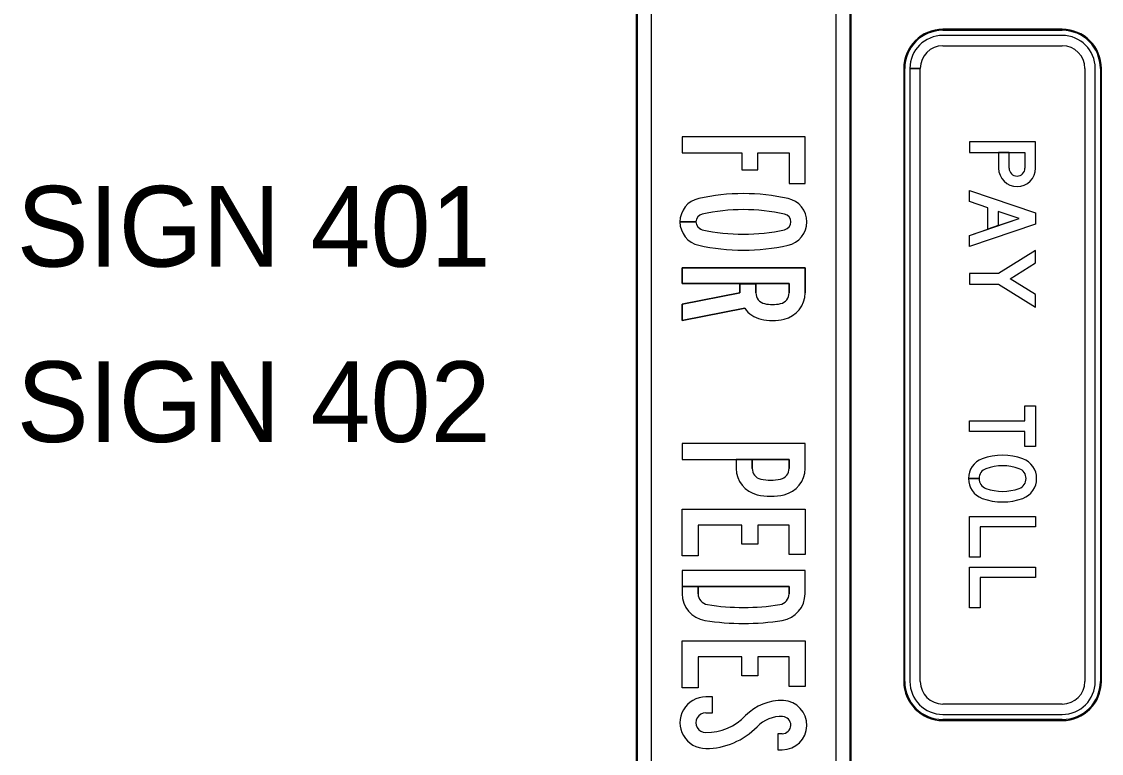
# Model space of a CAD drawing. Extents: x 524708 to 525491, y 1531861 to 1532506.
# Drawn here: x 525015.42 to 525062.25, y 1532201.55 to 1532233.31 of the extents above; entities that cross this region are included whole.
import ezdxf

# ---------------------------------------------------------------- set-up
doc = ezdxf.new("R2010")
doc.units = 0
for name, color, linetype in [('GSBWFill', 7, 'Continuous'), ('GSColorFill', 7, 'Continuous'), ('GSOutline', 7, 'Continuous'), ('TextLabel', 7, 'Continuous')]:
    doc.layers.add(name, color=color, linetype=linetype)

msp = doc.modelspace()

# ---------------------------------------------------------------- linework, layer by layer
at = {"layer": 'GSBWFill'}
for p, q in [((525058.932, 1532227.631), (525058.932, 1532226.945)), ((525044.663, 1532224.613), (525043.97, 1532224.613)), ((525043.97, 1532224.612), (525044.663, 1532224.612)), ((525046.57, 1532221.533), (525046.57, 1532221.932)), ((525046.41, 1532214.306), (525046.41, 1532213.916)), ((525056.939, 1532213.474), (525056.482, 1532213.474)), ((525056.482, 1532213.473), (525056.939, 1532213.473))]:
    msp.add_line(p, q, dxfattribs=at)
for points in [[(525044.063, 1532227.613), (525046.65, 1532227.613), (525046.65, 1532226.866), (525047.343, 1532226.866), (525047.343, 1532227.613), (525048.703, 1532227.613), (525048.703, 1532226.279), (525049.397, 1532226.279), (525049.397, 1532228.306), (525044.063, 1532228.306)], [(525056.532, 1532225.974), (525059.389, 1532225.002), (525059.389, 1532224.516), (525056.532, 1532223.545), (525056.532, 1532224.028), (525058.683, 1532224.759), (525057.774, 1532225.068), (525057.774, 1532224.45), (525057.317, 1532224.295), (525057.317, 1532225.224), (525056.532, 1532225.491)], [(525056.532, 1532222.374), (525056.532, 1532221.916), (525057.789, 1532221.916), (525059.389, 1532220.916), (525059.389, 1532221.455), (525058.286, 1532222.145), (525059.389, 1532222.834), (525059.389, 1532223.374), (525057.789, 1532222.374)], [(525059.389, 1532214.859), (525058.932, 1532214.859), (525058.932, 1532215.516), (525056.532, 1532215.516), (525056.532, 1532215.974), (525058.932, 1532215.974), (525058.932, 1532216.631), (525059.389, 1532216.631)], [(525049.397, 1532210.173), (525048.703, 1532210.173), (525048.703, 1532211.453), (525047.343, 1532211.453), (525047.343, 1532210.626), (525046.65, 1532210.626), (525046.65, 1532211.453), (525044.757, 1532211.453), (525044.757, 1532210.119), (525044.063, 1532210.119), (525044.063, 1532212.146), (525049.397, 1532212.146)], [(525056.989, 1532211.374), (525056.989, 1532210.059), (525056.532, 1532210.059), (525056.532, 1532211.831), (525059.389, 1532211.831), (525059.389, 1532211.374)], [(525056.989, 1532209.174), (525056.989, 1532207.859), (525056.532, 1532207.859), (525056.532, 1532209.631), (525059.389, 1532209.631), (525059.389, 1532209.174)], [(525049.397, 1532204.453), (525048.703, 1532204.453), (525048.703, 1532205.733), (525047.343, 1532205.733), (525047.343, 1532204.906), (525046.65, 1532204.906), (525046.65, 1532205.733), (525044.757, 1532205.733), (525044.757, 1532204.399), (525044.063, 1532204.399), (525044.063, 1532206.426), (525049.397, 1532206.426)]]:
    msp.add_lwpolyline(points, close=True, dxfattribs=at)
for points in [[(525059.389, 1532226.945), (525059.389, 1532228.088), (525056.532, 1532228.088), (525056.532, 1532227.631), (525058.932, 1532227.631)], [(525058.246, 1532226.945), (525058.246, 1532227.631), (525057.789, 1532227.631), (525057.789, 1532226.945)], [(525048.703, 1532221.533), (525048.703, 1532221.933), (525044.063, 1532221.933), (525044.063, 1532222.626), (525049.397, 1532222.626), (525049.397, 1532221.533)], [(525046.57, 1532221.932), (525047.263, 1532221.932), (525047.263, 1532221.533)], [(525046.778, 1532220.866), (525044.063, 1532220.333), (525044.063, 1532221.039), (525046.57, 1532221.532)], [(525049.397, 1532213.916), (525049.397, 1532214.999), (525044.063, 1532214.999), (525044.063, 1532214.306), (525048.703, 1532214.306), (525048.703, 1532213.916)], [(525047.103, 1532213.916), (525047.103, 1532214.306), (525046.41, 1532214.306)], [(525049.397, 1532208.477), (525049.397, 1532209.479), (525044.063, 1532209.479), (525044.063, 1532208.786), (525048.703, 1532208.786), (525048.703, 1532208.477)], [(525044.757, 1532208.477), (525044.757, 1532208.786), (525044.063, 1532208.786), (525044.063, 1532208.477)], [(525045.09, 1532203.306), (525045.383, 1532203.306), (525045.383, 1532203.999), (525045.09, 1532203.999)], [(525048.405, 1532202.399), (525048.218, 1532202.399), (525048.218, 1532201.706), (525048.405, 1532201.706)]]:
    msp.add_lwpolyline(points, dxfattribs=at)
for centre, radius, start, end in [((525058.589, 1532226.945), 0.8, 180, 0), ((525058.589, 1532226.945), 0.343, 180, 0), ((525047.743, 1532221.533), 1.173, 180, 180.082), ((525047.743, 1532221.533), 0.48, 180, 256.9971), ((525048.223, 1532221.533), 0.48, 283.0029, 0), ((525048.223, 1532221.533), 1.173, 283.0029, 0), ((525047.743, 1532221.533), 1.173, 214.6641, 256.9971), ((525047.983, 1532222.573), 1.547, 256.9971, 283.0029), ((525047.983, 1532222.573), 2.24, 256.9971, 283.0029)]:
    msp.add_arc(centre, radius, start, end, dxfattribs=at)
for centre, major_axis, ratio, start_param, end_param in [((525046.721, 1532216.867), (8.972, 0), 0.999991, 1.353418, 1.788175), ((525045.01, 1532224.613), (1.04, 0), 0.999991, 1.788175, 3.141593), ((525048.431, 1532224.613), (1.04, 0), 0.999991, 4.929767, 7.636603), ((525045.01, 1532224.613), (0.347, 0), 0.999991, 1.788175, 3.141593), ((525046.721, 1532216.867), (8.279, 0), 0.999991, 1.353418, 1.788175), ((525048.431, 1532224.613), (0.347, 0), 0.999991, 4.929767, 7.636603), ((525045.01, 1532224.613), (1.04, 0), 0.999991, 3.141849, 4.495011), ((525045.01, 1532224.613), (0.347, 0), 0.999991, 3.142362, 4.495011), ((525046.721, 1532232.358), (8.279, 0), 0.999991, 4.495011, 4.929767), ((525046.721, 1532232.358), (8.972, 0), 0.999991, 4.495011, 4.929767), ((525057.396, 1532213.474), (0.914, 0), 0.999998, 1.921585, 3.141593), ((525057.96, 1532211.931), (2.556, 0), 0.999998, 1.220008, 1.921585), ((525058.525, 1532213.474), (0.914, 0), 0.999998, 5.063177, 7.503193), ((525047.583, 1532213.916), (1.173, 0), 0.999996, 3.141593, 4.483993), ((525047.583, 1532213.916), (0.48, 0), 0.999996, 3.141593, 4.483993), ((525048.223, 1532213.916), (0.48, 0), 0.999996, 4.940785, 6.283185), ((525048.223, 1532213.916), (1.173, 0), 0.999996, 4.940785, 6.283185), ((525057.396, 1532213.474), (0.457, 0), 0.999998, 1.921585, 3.141593), ((525057.96, 1532211.931), (2.099, 0), 0.999998, 1.220008, 1.921585), ((525058.525, 1532213.474), (0.457, 0), 0.999998, 5.063177, 7.503193), ((525047.903, 1532215.293), (1.893, 0), 0.999996, 4.483993, 4.940785), ((525057.396, 1532213.474), (0.914, 0), 0.999998, 3.141749, 4.361601), ((525057.396, 1532213.474), (0.457, 0), 0.999998, 3.141905, 4.361601), ((525047.903, 1532215.293), (2.587, 0), 0.999996, 4.483993, 4.940785), ((525057.96, 1532215.016), (2.099, 0), 0.999998, 4.361601, 5.063177), ((525057.96, 1532215.016), (2.556, 0), 0.999998, 4.361601, 5.063177), ((525045.237, 1532208.477), (1.173, 0), 0.999996, 3.141593, 4.55443), ((525045.237, 1532208.477), (0.48, 0), 0.999996, 3.141593, 4.55443), ((525048.223, 1532208.477), (0.48, 0), 0.999996, 4.870348, 6.283185), ((525048.223, 1532208.477), (1.173, 0), 0.999996, 4.870348, 6.283185), ((525046.73, 1532217.853), (9.973, 0), 0.999996, 4.55443, 4.870348), ((525046.73, 1532217.853), (10.667, 0), 0.999996, 4.55443, 4.870348), ((525045.09, 1532202.879), (1.12, 0), 0.99999, 1.570796, 4.712389), ((525048.355, 1532201.707), (2.133, 0), 0.99999, 1.523757, 2.374761), ((525048.405, 1532202.773), (1.067, 0), 0.99999, 4.712389, 7.806942), ((525045.09, 1532202.879), (0.427, 0), 0.99999, 1.570796, 4.712389), ((525045.09, 1532204.853), (2.4, 0), 0.99999, 4.712389, 5.516353), ((525048.355, 1532201.707), (1.44, 0), 0.99999, 1.523757, 2.374761), ((525048.405, 1532202.773), (0.373, 0), 0.99999, 4.712389, 7.806942), ((525045.09, 1532204.853), (3.093, 0), 0.99999, 4.712389, 5.516353)]:
    msp.add_ellipse(centre, major_axis=major_axis, ratio=ratio, start_param=start_param, end_param=end_param, dxfattribs=at)
at = {"layer": 'GSColorFill'}
for p, q in [((525042.068, 1532248.424), (525042.068, 1532185.757)), ((525042.068, 1532248.423), (525042.068, 1532185.757)), ((525042.068, 1532248.417), (525042.068, 1532185.757)), ((525042.134, 1532185.757), (525042.134, 1532248.423)), ((525042.734, 1532185.757), (525042.734, 1532248.417)), ((525050.734, 1532248.424), (525050.734, 1532185.757)), ((525051.334, 1532248.424), (525051.334, 1532185.757)), ((525051.401, 1532185.757), (525051.401, 1532248.424)), ((525051.401, 1532185.757), (525051.401, 1532248.424)), ((525051.401, 1532185.757), (525051.401, 1532248.424)), ((525060.55, 1532232.973), (525055.372, 1532232.973)), ((525060.55, 1532232.973), (525055.372, 1532232.973)), ((525055.372, 1532232.928), (525060.55, 1532232.928)), ((525060.55, 1532232.705), (525055.372, 1532232.705)), ((525055.372, 1532232.259), (525060.55, 1532232.259)), ((525053.675, 1532231.276), (525053.675, 1532204.669)), ((525053.675, 1532231.276), (525053.72, 1532231.276)), ((525053.72, 1532231.276), (525053.675, 1532231.276)), ((525053.675, 1532231.276), (525053.675, 1532204.669)), ((525053.72, 1532204.669), (525053.72, 1532231.276)), ((525053.943, 1532231.276), (525054.389, 1532231.276)), ((525053.943, 1532231.272), (525053.943, 1532204.669)), ((525054.389, 1532231.272), (525053.943, 1532231.272)), ((525054.389, 1532204.669), (525054.389, 1532231.272)), ((525061.532, 1532231.276), (525061.532, 1532204.669)), ((525061.979, 1532204.669), (525061.979, 1532231.276)), ((525062.202, 1532231.276), (525062.202, 1532204.669)), ((525062.247, 1532204.669), (525062.247, 1532231.276)), ((525062.247, 1532204.669), (525062.247, 1532231.276)), ((525058.932, 1532227.631), (525058.932, 1532226.945)), ((525044.663, 1532224.613), (525043.97, 1532224.613)), ((525043.97, 1532224.612), (525044.663, 1532224.612)), ((525046.57, 1532221.533), (525046.57, 1532221.932)), ((525046.41, 1532214.306), (525046.41, 1532213.916)), ((525056.939, 1532213.474), (525056.482, 1532213.474)), ((525056.482, 1532213.473), (525056.939, 1532213.473)), ((525060.55, 1532203.687), (525055.372, 1532203.687)), ((525055.372, 1532203.241), (525060.55, 1532203.241)), ((525060.55, 1532203.018), (525055.372, 1532203.018)), ((525055.372, 1532202.973), (525060.55, 1532202.973)), ((525055.372, 1532202.973), (525060.55, 1532202.973))]:
    msp.add_line(p, q, dxfattribs=at)
for points in [[(525044.063, 1532227.613), (525046.65, 1532227.613), (525046.65, 1532226.866), (525047.343, 1532226.866), (525047.343, 1532227.613), (525048.703, 1532227.613), (525048.703, 1532226.279), (525049.397, 1532226.279), (525049.397, 1532228.306), (525044.063, 1532228.306)], [(525056.532, 1532225.974), (525059.389, 1532225.002), (525059.389, 1532224.516), (525056.532, 1532223.545), (525056.532, 1532224.028), (525058.683, 1532224.759), (525057.774, 1532225.068), (525057.774, 1532224.45), (525057.317, 1532224.295), (525057.317, 1532225.224), (525056.532, 1532225.491)], [(525056.532, 1532222.374), (525056.532, 1532221.916), (525057.789, 1532221.916), (525059.389, 1532220.916), (525059.389, 1532221.455), (525058.286, 1532222.145), (525059.389, 1532222.834), (525059.389, 1532223.374), (525057.789, 1532222.374)], [(525059.389, 1532214.859), (525058.932, 1532214.859), (525058.932, 1532215.516), (525056.532, 1532215.516), (525056.532, 1532215.974), (525058.932, 1532215.974), (525058.932, 1532216.631), (525059.389, 1532216.631)], [(525049.397, 1532210.173), (525048.703, 1532210.173), (525048.703, 1532211.453), (525047.343, 1532211.453), (525047.343, 1532210.626), (525046.65, 1532210.626), (525046.65, 1532211.453), (525044.757, 1532211.453), (525044.757, 1532210.119), (525044.063, 1532210.119), (525044.063, 1532212.146), (525049.397, 1532212.146)], [(525056.989, 1532211.374), (525056.989, 1532210.059), (525056.532, 1532210.059), (525056.532, 1532211.831), (525059.389, 1532211.831), (525059.389, 1532211.374)], [(525056.989, 1532209.174), (525056.989, 1532207.859), (525056.532, 1532207.859), (525056.532, 1532209.631), (525059.389, 1532209.631), (525059.389, 1532209.174)], [(525049.397, 1532204.453), (525048.703, 1532204.453), (525048.703, 1532205.733), (525047.343, 1532205.733), (525047.343, 1532204.906), (525046.65, 1532204.906), (525046.65, 1532205.733), (525044.757, 1532205.733), (525044.757, 1532204.399), (525044.063, 1532204.399), (525044.063, 1532206.426), (525049.397, 1532206.426)]]:
    msp.add_lwpolyline(points, close=True, dxfattribs=at)
for points in [[(525059.389, 1532226.945), (525059.389, 1532228.088), (525056.532, 1532228.088), (525056.532, 1532227.631), (525058.932, 1532227.631)], [(525058.246, 1532226.945), (525058.246, 1532227.631), (525057.789, 1532227.631), (525057.789, 1532226.945)], [(525048.703, 1532221.533), (525048.703, 1532221.933), (525044.063, 1532221.933), (525044.063, 1532222.626), (525049.397, 1532222.626), (525049.397, 1532221.533)], [(525046.57, 1532221.932), (525047.263, 1532221.932), (525047.263, 1532221.533)], [(525046.778, 1532220.866), (525044.063, 1532220.333), (525044.063, 1532221.039), (525046.57, 1532221.532)], [(525049.397, 1532213.916), (525049.397, 1532214.999), (525044.063, 1532214.999), (525044.063, 1532214.306), (525048.703, 1532214.306), (525048.703, 1532213.916)], [(525047.103, 1532213.916), (525047.103, 1532214.306), (525046.41, 1532214.306)], [(525049.397, 1532208.477), (525049.397, 1532209.479), (525044.063, 1532209.479), (525044.063, 1532208.786), (525048.703, 1532208.786), (525048.703, 1532208.477)], [(525044.757, 1532208.477), (525044.757, 1532208.786), (525044.063, 1532208.786), (525044.063, 1532208.477)], [(525045.09, 1532203.306), (525045.383, 1532203.306), (525045.383, 1532203.999), (525045.09, 1532203.999)], [(525048.405, 1532202.399), (525048.218, 1532202.399), (525048.218, 1532201.706), (525048.405, 1532201.706)]]:
    msp.add_lwpolyline(points, dxfattribs=at)
for centre, radius, start, end in [((525055.372, 1532231.276), 1.696, 90, 180), ((525055.372, 1532231.276), 1.696, 90, 180), ((525055.372, 1532231.276), 1.652, 90, 180), ((525060.55, 1532231.276), 1.696, 0, 90), ((525060.55, 1532231.276), 1.696, 0, 90), ((525060.55, 1532231.276), 1.652, 0, 90), ((525055.372, 1532231.276), 1.429, 90, 180), ((525060.55, 1532231.276), 1.429, 0, 90), ((525055.372, 1532231.276), 0.982, 90, 180), ((525060.55, 1532231.276), 0.982, 0, 90), ((525058.589, 1532226.945), 0.8, 180, 0), ((525058.589, 1532226.945), 0.343, 180, 0), ((525047.743, 1532221.533), 1.173, 180, 180.082), ((525047.743, 1532221.533), 0.48, 180, 256.9971), ((525048.223, 1532221.533), 0.48, 283.0029, 0), ((525048.223, 1532221.533), 1.173, 283.0029, 0), ((525047.743, 1532221.533), 1.173, 214.6641, 256.9971), ((525047.983, 1532222.573), 1.547, 256.9971, 283.0029), ((525047.983, 1532222.573), 2.24, 256.9971, 283.0029), ((525055.372, 1532204.669), 1.696, 180, 270), ((525055.372, 1532204.669), 1.696, 180, 270), ((525055.372, 1532204.669), 1.652, 180, 270), ((525055.372, 1532204.669), 1.429, 180, 270), ((525055.372, 1532204.669), 0.982, 180, 270), ((525060.55, 1532204.669), 1.429, 270, 0), ((525060.55, 1532204.669), 0.982, 270, 0), ((525060.55, 1532204.669), 1.696, 270, 0), ((525060.55, 1532204.669), 1.652, 270, 0), ((525060.55, 1532204.669), 1.696, 270, 0)]:
    msp.add_arc(centre, radius, start, end, dxfattribs=at)
for centre, major_axis, ratio, start_param, end_param in [((525046.721, 1532216.867), (8.972, 0), 0.999991, 1.353418, 1.788175), ((525045.01, 1532224.613), (1.04, 0), 0.999991, 1.788175, 3.141593), ((525048.431, 1532224.613), (1.04, 0), 0.999991, 4.929767, 7.636603), ((525045.01, 1532224.613), (0.347, 0), 0.999991, 1.788175, 3.141593), ((525046.721, 1532216.867), (8.279, 0), 0.999991, 1.353418, 1.788175), ((525048.431, 1532224.613), (0.347, 0), 0.999991, 4.929767, 7.636603), ((525045.01, 1532224.613), (1.04, 0), 0.999991, 3.141849, 4.495011), ((525045.01, 1532224.613), (0.347, 0), 0.999991, 3.142362, 4.495011), ((525046.721, 1532232.358), (8.279, 0), 0.999991, 4.495011, 4.929767), ((525046.721, 1532232.358), (8.972, 0), 0.999991, 4.495011, 4.929767), ((525057.396, 1532213.474), (0.914, 0), 0.999998, 1.921585, 3.141593), ((525057.96, 1532211.931), (2.556, 0), 0.999998, 1.220008, 1.921585), ((525058.525, 1532213.474), (0.914, 0), 0.999998, 5.063177, 7.503193), ((525047.583, 1532213.916), (1.173, 0), 0.999996, 3.141593, 4.483993), ((525047.583, 1532213.916), (0.48, 0), 0.999996, 3.141593, 4.483993), ((525048.223, 1532213.916), (0.48, 0), 0.999996, 4.940785, 6.283185), ((525048.223, 1532213.916), (1.173, 0), 0.999996, 4.940785, 6.283185), ((525057.396, 1532213.474), (0.457, 0), 0.999998, 1.921585, 3.141593), ((525057.96, 1532211.931), (2.099, 0), 0.999998, 1.220008, 1.921585), ((525058.525, 1532213.474), (0.457, 0), 0.999998, 5.063177, 7.503193), ((525047.903, 1532215.293), (1.893, 0), 0.999996, 4.483993, 4.940785), ((525057.396, 1532213.474), (0.914, 0), 0.999998, 3.141749, 4.361601), ((525057.396, 1532213.474), (0.457, 0), 0.999998, 3.141905, 4.361601), ((525047.903, 1532215.293), (2.587, 0), 0.999996, 4.483993, 4.940785), ((525057.96, 1532215.016), (2.099, 0), 0.999998, 4.361601, 5.063177), ((525057.96, 1532215.016), (2.556, 0), 0.999998, 4.361601, 5.063177), ((525045.237, 1532208.477), (1.173, 0), 0.999996, 3.141593, 4.55443), ((525045.237, 1532208.477), (0.48, 0), 0.999996, 3.141593, 4.55443), ((525048.223, 1532208.477), (0.48, 0), 0.999996, 4.870348, 6.283185), ((525048.223, 1532208.477), (1.173, 0), 0.999996, 4.870348, 6.283185), ((525046.73, 1532217.853), (9.973, 0), 0.999996, 4.55443, 4.870348), ((525046.73, 1532217.853), (10.667, 0), 0.999996, 4.55443, 4.870348), ((525045.09, 1532202.879), (1.12, 0), 0.99999, 1.570796, 4.712389), ((525048.355, 1532201.707), (2.133, 0), 0.99999, 1.523757, 2.374761), ((525048.405, 1532202.773), (1.067, 0), 0.99999, 4.712389, 7.806942), ((525045.09, 1532202.879), (0.427, 0), 0.99999, 1.570796, 4.712389), ((525045.09, 1532204.853), (2.4, 0), 0.99999, 4.712389, 5.516353), ((525048.355, 1532201.707), (1.44, 0), 0.99999, 1.523757, 2.374761), ((525048.405, 1532202.773), (0.373, 0), 0.99999, 4.712389, 7.806942), ((525045.09, 1532204.853), (3.093, 0), 0.99999, 4.712389, 5.516353)]:
    msp.add_ellipse(centre, major_axis=major_axis, ratio=ratio, start_param=start_param, end_param=end_param, dxfattribs=at)
at = {"layer": 'GSOutline'}
for p, q in [((525057.789, 1532227.631), (525057.789, 1532226.945)), ((525046.57, 1532221.933), (525046.57, 1532221.533)), ((525048.703, 1532213.916), (525048.703, 1532214.306)), ((525044.757, 1532208.786), (525044.757, 1532208.477))]:
    msp.add_line(p, q, dxfattribs=at)
for points in [[(525044.063, 1532227.613), (525046.65, 1532227.613), (525046.65, 1532226.866), (525047.343, 1532226.866), (525047.343, 1532227.613), (525048.703, 1532227.613), (525048.703, 1532226.279), (525049.397, 1532226.279), (525049.397, 1532228.306), (525044.063, 1532228.306)], [(525057.317, 1532225.224), (525056.532, 1532225.491), (525056.532, 1532225.974), (525059.389, 1532225.002), (525059.389, 1532224.516), (525056.532, 1532223.545), (525056.532, 1532224.028), (525057.317, 1532224.295)], [(525057.774, 1532225.068), (525057.774, 1532224.45), (525058.683, 1532224.759)], [(525056.532, 1532222.374), (525056.532, 1532221.916), (525057.789, 1532221.916), (525059.389, 1532220.916), (525059.389, 1532221.455), (525058.286, 1532222.145), (525059.389, 1532222.834), (525059.389, 1532223.374), (525057.789, 1532222.374)], [(525059.389, 1532214.859), (525058.932, 1532214.859), (525058.932, 1532215.516), (525056.532, 1532215.516), (525056.532, 1532215.974), (525058.932, 1532215.974), (525058.932, 1532216.631), (525059.389, 1532216.631)], [(525049.397, 1532210.173), (525048.703, 1532210.173), (525048.703, 1532211.453), (525047.343, 1532211.453), (525047.343, 1532210.626), (525046.65, 1532210.626), (525046.65, 1532211.453), (525044.757, 1532211.453), (525044.757, 1532210.119), (525044.063, 1532210.119), (525044.063, 1532212.146), (525049.397, 1532212.146)], [(525056.989, 1532211.374), (525056.989, 1532210.059), (525056.532, 1532210.059), (525056.532, 1532211.831), (525059.389, 1532211.831), (525059.389, 1532211.374)], [(525056.989, 1532209.174), (525056.989, 1532207.859), (525056.532, 1532207.859), (525056.532, 1532209.631), (525059.389, 1532209.631), (525059.389, 1532209.174)], [(525049.397, 1532204.453), (525048.703, 1532204.453), (525048.703, 1532205.733), (525047.343, 1532205.733), (525047.343, 1532204.906), (525046.65, 1532204.906), (525046.65, 1532205.733), (525044.757, 1532205.733), (525044.757, 1532204.399), (525044.063, 1532204.399), (525044.063, 1532206.426), (525049.397, 1532206.426)]]:
    msp.add_lwpolyline(points, close=True, dxfattribs=at)
for points in [[(525059.389, 1532226.945), (525059.389, 1532228.088), (525056.532, 1532228.088), (525056.532, 1532227.631), (525057.789, 1532227.631)], [(525058.246, 1532226.945), (525058.246, 1532227.631), (525058.932, 1532227.631), (525058.932, 1532226.945)], [(525049.397, 1532221.533), (525049.397, 1532222.626), (525044.063, 1532222.626), (525044.063, 1532221.933), (525046.57, 1532221.933)], [(525047.263, 1532221.533), (525047.263, 1532221.933), (525048.703, 1532221.933), (525048.703, 1532221.533)], [(525046.57, 1532221.532), (525044.063, 1532221.039), (525044.063, 1532220.333), (525046.778, 1532220.866)], [(525049.397, 1532213.916), (525049.397, 1532214.999), (525044.063, 1532214.999), (525044.063, 1532214.306)], [(525044.063, 1532214.306), (525046.41, 1532214.306), (525046.41, 1532213.916)], [(525048.703, 1532214.306), (525047.103, 1532214.306), (525047.103, 1532213.916)], [(525049.397, 1532208.477), (525049.397, 1532209.479), (525044.063, 1532209.479), (525044.063, 1532208.477)], [(525048.703, 1532208.477), (525048.703, 1532208.786), (525044.757, 1532208.786)], [(525045.09, 1532203.306), (525045.383, 1532203.306), (525045.383, 1532203.999), (525045.09, 1532203.999)], [(525048.405, 1532202.399), (525048.218, 1532202.399), (525048.218, 1532201.706), (525048.405, 1532201.706)]]:
    msp.add_lwpolyline(points, dxfattribs=at)
for centre, radius, start, end in [((525058.589, 1532226.945), 0.8, 180, 0), ((525058.589, 1532226.945), 0.343, 180, 0), ((525047.743, 1532221.533), 1.173, 180, 180.082), ((525047.743, 1532221.533), 0.48, 180, 256.9971), ((525048.223, 1532221.533), 0.48, 283.0029, 0), ((525048.223, 1532221.533), 1.173, 283.0029, 0), ((525047.743, 1532221.533), 1.173, 214.6641, 256.9971), ((525047.983, 1532222.573), 1.547, 256.9971, 283.0029), ((525047.983, 1532222.573), 2.24, 256.9971, 283.0029)]:
    msp.add_arc(centre, radius, start, end, dxfattribs=at)
for centre, major_axis, ratio, start_param, end_param in [((525046.721, 1532216.867), (8.972, 0), 0.999991, 1.353418, 1.788175), ((525045.01, 1532224.613), (1.04, 0), 0.999991, 1.788175, 4.495011), ((525048.431, 1532224.613), (1.04, 0), 0.999991, 4.929767, 7.636603), ((525045.01, 1532224.613), (0.347, 0), 0.999991, 1.788175, 4.495011), ((525046.721, 1532216.867), (8.279, 0), 0.999991, 1.353418, 1.788175), ((525048.431, 1532224.613), (0.347, 0), 0.999991, 4.929767, 7.636603), ((525046.721, 1532232.358), (8.279, 0), 0.999991, 4.495011, 4.929767), ((525046.721, 1532232.358), (8.972, 0), 0.999991, 4.495011, 4.929767), ((525057.396, 1532213.474), (0.914, 0), 0.999998, 1.921585, 4.361601), ((525057.96, 1532211.931), (2.556, 0), 0.999998, 1.220008, 1.921585), ((525058.525, 1532213.474), (0.914, 0), 0.999998, 5.063177, 7.503193), ((525047.583, 1532213.916), (1.173, 0), 0.999996, 3.141593, 4.483993), ((525047.583, 1532213.916), (0.48, 0), 0.999996, 3.141593, 4.483993), ((525048.223, 1532213.916), (0.48, 0), 0.999996, 4.940785, 6.283185), ((525048.223, 1532213.916), (1.173, 0), 0.999996, 4.940785, 6.283185), ((525057.396, 1532213.474), (0.457, 0), 0.999998, 1.921585, 4.361601), ((525057.96, 1532211.931), (2.099, 0), 0.999998, 1.220008, 1.921585), ((525058.525, 1532213.474), (0.457, 0), 0.999998, 5.063177, 7.503193), ((525047.903, 1532215.293), (1.893, 0), 0.999996, 4.483993, 4.940785), ((525047.903, 1532215.293), (2.587, 0), 0.999996, 4.483993, 4.940785), ((525057.96, 1532215.016), (2.099, 0), 0.999998, 4.361601, 5.063177), ((525057.96, 1532215.016), (2.556, 0), 0.999998, 4.361601, 5.063177), ((525045.237, 1532208.477), (1.173, 0), 0.999996, 3.141593, 4.55443), ((525045.237, 1532208.477), (0.48, 0), 0.999996, 3.141593, 4.55443), ((525048.223, 1532208.477), (0.48, 0), 0.999996, 4.870348, 6.283185), ((525048.223, 1532208.477), (1.173, 0), 0.999996, 4.870348, 6.283185), ((525046.73, 1532217.853), (9.973, 0), 0.999996, 4.55443, 4.870348), ((525046.73, 1532217.853), (10.667, 0), 0.999996, 4.55443, 4.870348), ((525045.09, 1532202.879), (1.12, 0), 0.99999, 1.570796, 4.712389), ((525048.355, 1532201.707), (2.133, 0), 0.99999, 1.523757, 2.374761), ((525048.405, 1532202.773), (1.067, 0), 0.99999, 4.712389, 7.806942), ((525045.09, 1532202.879), (0.427, 0), 0.99999, 1.570796, 4.712389), ((525045.09, 1532204.853), (2.4, 0), 0.99999, 4.712389, 5.516353), ((525048.355, 1532201.707), (1.44, 0), 0.99999, 1.523757, 2.374761), ((525048.405, 1532202.773), (0.373, 0), 0.99999, 4.712389, 7.806942), ((525045.09, 1532204.853), (3.093, 0), 0.99999, 4.712389, 5.516353)]:
    msp.add_ellipse(centre, major_axis=major_axis, ratio=ratio, start_param=start_param, end_param=end_param, dxfattribs=at)

# ---------------------------------------------------------------- texts
at = {"layer": 'TextLabel'}
for s, p in [('SIGN 401', (525015.206, 1532222.673)), ('SIGN 402', (525015.206, 1532215.06))]:
    msp.add_text(s, height=3.5, dxfattribs=at).set_placement(p)

doc.saveas('drawing.dxf')
